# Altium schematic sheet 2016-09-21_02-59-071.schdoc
size 285 x 125 mm; SheetNumber: 1; SheetTotal: 1
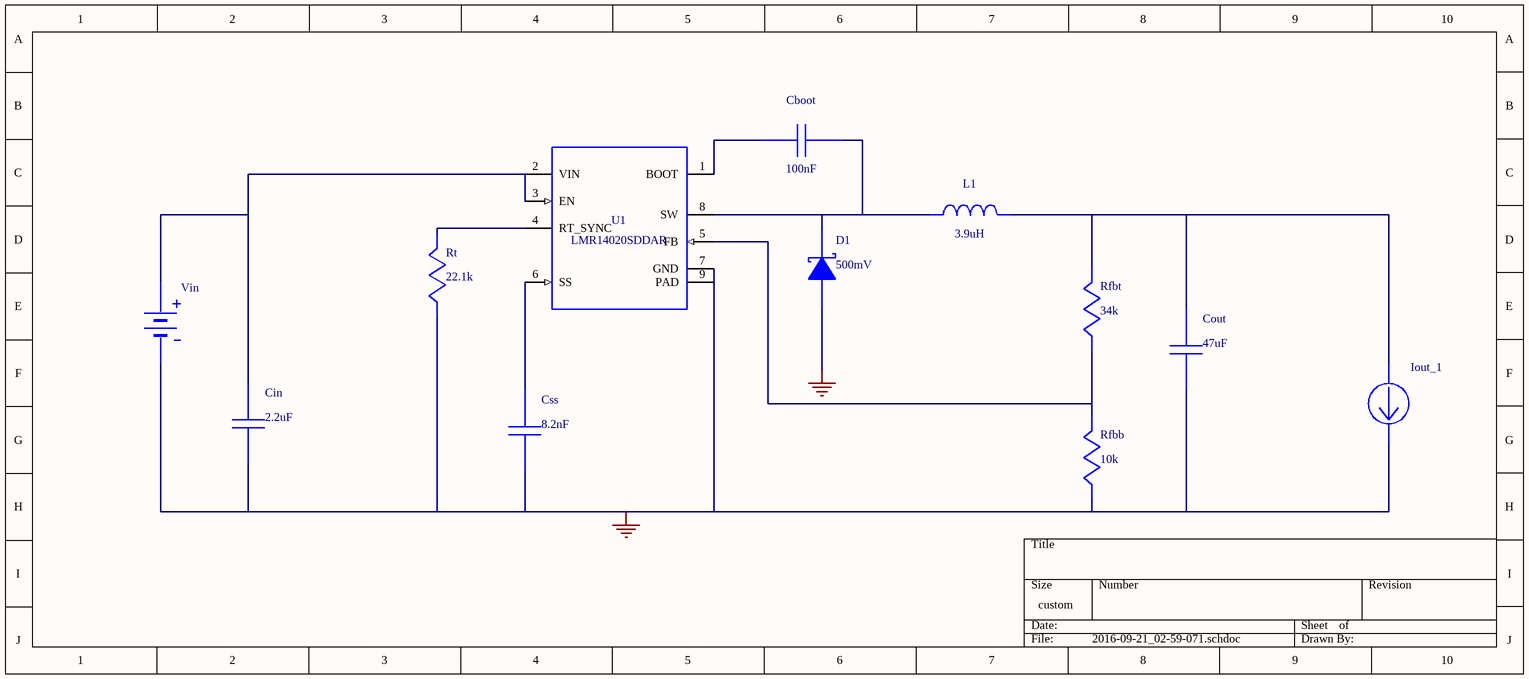
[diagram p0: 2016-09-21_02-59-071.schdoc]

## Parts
Cboot  value 100nF  (hidden comment: C0805C104K5RACTU)
Cin  value 2.2uF  (hidden comment: GRM31CR71H225KA88L)
Cout  value 47uF  (hidden comment: GRM31CR61A476KE15L)
Css  value 8.2nF  (hidden comment: GRM155R71C822KA01D)
D1  value 500mV  (hidden comment: B340A-13-F)
Iout_1  WB_CURRENT_LOAD  (value not drawn)
L1  value 3.9uH  (hidden comment: SRU8043-3R9Y)
Rfbb  value 10k  (hidden comment: CRCW040210K0FKED)
Rfbt  value 34k  (hidden comment: CRCW040234K0FKED)
Rt  value 22.1k  (hidden comment: CRCW040222K1FKED)
U1  LMR14020SDDAR
Vin  WB_BATTERY  (value not drawn)

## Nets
0: Cin.2 Cout.2 Css.2 D1.2(A) Iout_1.2(-) Rfbb.2 Rt.2 U1.7(GND) U1.9(PAD) Vin.2(-)
NetCboot_1: Cboot.1 U1.1(BOOT)
NetCboot_2: Cboot.2 D1.1(K) L1.1 U1.8(SW)
NetCin_1: Cin.1 U1.2(VIN) U1.3(EN) Vin.1(+)
NetCout_1: Cout.1 Iout_1.1(+) L1.2 Rfbt.1
NetCss_1: Css.1 U1.6(SS)
NetRfbb_1: Rfbb.1 Rfbt.2 U1.5(FB)
NetRt_1: Rt.1 U1.4(RT_SYNC)

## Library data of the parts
Cboot = C0805C104K5RACTU: Manufacturer Name: Kemet
Cin = GRM31CR71H225KA88L: GRM31CR71H225KA8; Manufacturer Name: MuRata
Cout = GRM31CR61A476KE15L: GRM31CR61A476KE1; Manufacturer Name: MuRata
Css = GRM155R71C822KA01D: GRM155R71C822KA0; Manufacturer Name: MuRata
D1 = B340A-13-F: Manufacturer Name: Diodes Inc.
L1 = SRU8043-3R9Y: Manufacturer Name: Bourns
Rfbb = CRCW040210K0FKED: Manufacturer Name: Vishay-Dale
Rfbt = CRCW040234K0FKED: Manufacturer Name: Vishay-Dale
Rt = CRCW040222K1FKED: Manufacturer Name: Vishay-Dale
U1 = LMR14020SDDAR: Manufacturer Name: Texas Instruments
